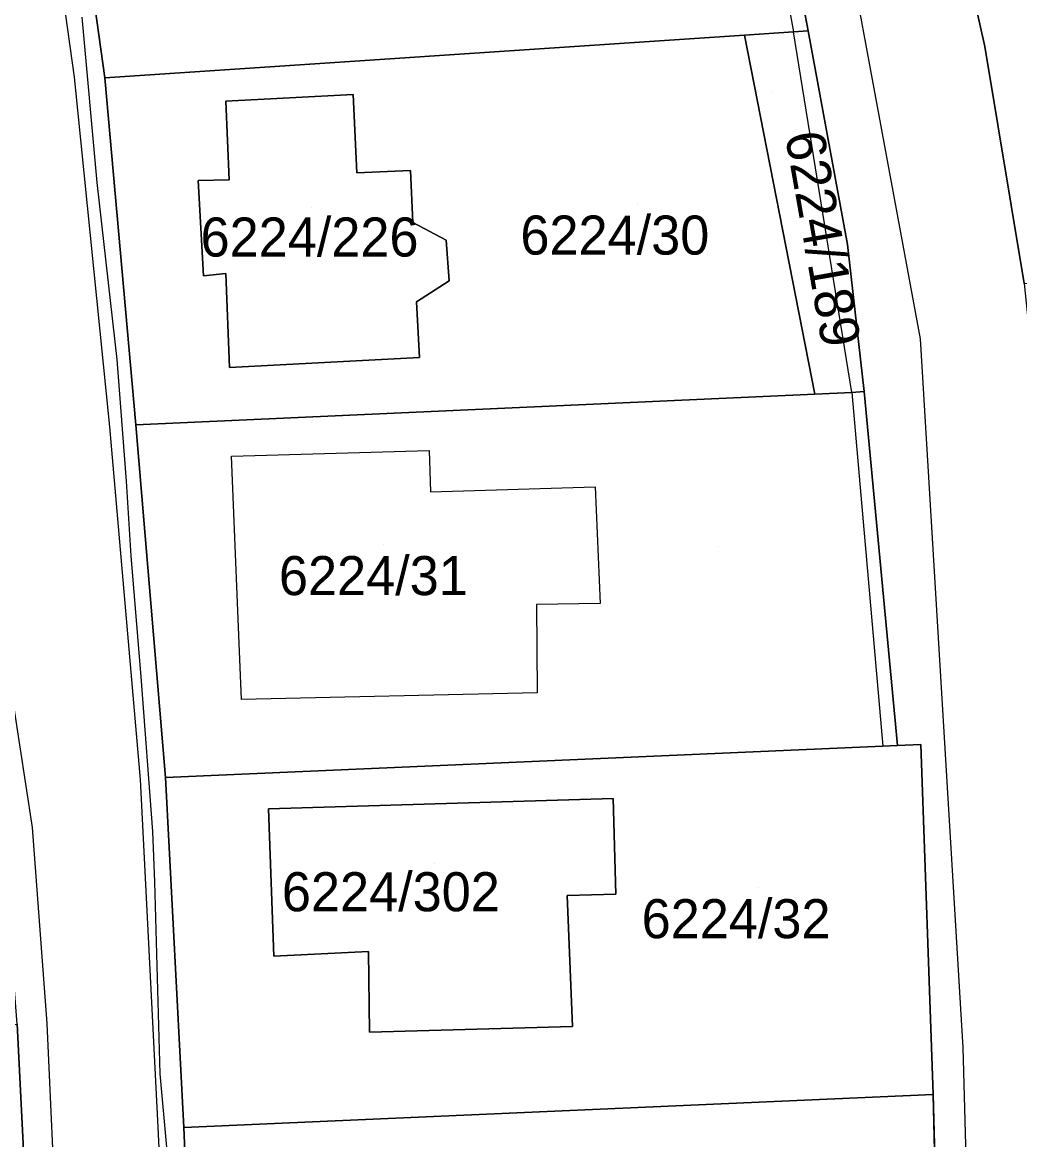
# Model space of a CAD drawing. Extents: x -266199 to -261993, y -1239047 to -1235108.
# Drawn here: x -263953.2 to -263902.2, y -1236099.8 to -1236042.6 of the extents above; entities that cross this region are included whole.
import ezdxf

# ---------------------------------------------------------------- set-up
doc = ezdxf.new("R2010")
doc.units = 0
for name, color, linetype in [('body_kn', 7, 'Continuous'), ('kladpar_druhypozemkov', 7, 'Continuous'), ('kladpar_hranice', 7, 'Continuous'), ('kladpar_parcelnecisla', 7, 'Continuous'), ('kladpar_plochy', 7, 'Continuous'), ('tarchy_linie', 7, 'Continuous'), ('zappar_hrandruhpozemk', 7, 'Continuous')]:
    doc.layers.add(name, color=color, linetype=linetype)

msp = doc.modelspace()

# ---------------------------------------------------------------- linework, layer by layer
at = {"layer": 'body_kn'}
for p, q in [((-263916.29, -1236043.3), (-263916.29, -1236043.3)), ((-263916.29, -1236043.3), (-263916.29, -1236043.3)), ((-263913.78, -1236043.13), (-263913.78, -1236043.13)), ((-263913.03, -1236043.08), (-263913.03, -1236043.08)), ((-263913.03, -1236043.08), (-263913.03, -1236043.08)), ((-263903.98, -1236043.88), (-263903.98, -1236043.88)), ((-263950.6, -1236045.45), (-263950.6, -1236045.45)), ((-263949.02, -1236045.48), (-263949.02, -1236045.48)), ((-263936.31, -1236046.34), (-263936.31, -1236046.34)), ((-263942.83, -1236046.68), (-263942.83, -1236046.68)), ((-263936.13, -1236050.35), (-263936.13, -1236050.35)), ((-263933.39, -1236050.22), (-263933.39, -1236050.22)), ((-263949.44, -1236050.84), (-263949.44, -1236050.84)), ((-263944.25, -1236050.74), (-263944.25, -1236050.74)), ((-263942.67, -1236050.71), (-263942.67, -1236050.71)), ((-263933.27, -1236052.89), (-263933.27, -1236052.89)), ((-263931.55, -1236053.79), (-263931.55, -1236053.79)), ((-263911.02, -1236054.02), (-263911.02, -1236054.02)), ((-263942.83, -1236055.5), (-263942.83, -1236055.5)), ((-263943.98, -1236055.62), (-263943.98, -1236055.62)), ((-263931.41, -1236055.87), (-263931.41, -1236055.87)), ((-263933.08, -1236056.95), (-263933.08, -1236056.95)), ((-263907.3, -1236058.84), (-263907.3, -1236058.84)), ((-263948.41, -1236059.9), (-263948.41, -1236059.9)), ((-263932.93, -1236059.79), (-263932.93, -1236059.79)), ((-263932.93, -1236059.79), (-263932.93, -1236059.79)), ((-263942.65, -1236060.31), (-263942.65, -1236060.31)), ((-263912.68, -1236061.67), (-263912.68, -1236061.67)), ((-263912.68, -1236061.67), (-263912.68, -1236061.67)), ((-263910.8, -1236061.59), (-263910.8, -1236061.59)), ((-263910.8, -1236061.59), (-263910.8, -1236061.59)), ((-263910.17, -1236061.54), (-263910.17, -1236061.54)), ((-263910.17, -1236061.54), (-263910.17, -1236061.54)), ((-263948.79, -1236063.35), (-263948.79, -1236063.35)), ((-263947.44, -1236063.25), (-263947.44, -1236063.25)), ((-263932.42, -1236064.56), (-263932.42, -1236064.56)), ((-263932.42, -1236064.56), (-263932.42, -1236064.56)), ((-263942.55, -1236064.85), (-263942.55, -1236064.85)), ((-263947.94, -1236066.13), (-263947.94, -1236066.13)), ((-263932.36, -1236066.67), (-263932.36, -1236066.67)), ((-263923.93, -1236066.41), (-263923.93, -1236066.41)), ((-263947.7, -1236069.95), (-263947.7, -1236069.95)), ((-263926.94, -1236072.44), (-263926.94, -1236072.44)), ((-263923.68, -1236072.38), (-263923.68, -1236072.38)), ((-263942.17, -1236074.01), (-263942.17, -1236074.01)), ((-263947.19, -1236076.14), (-263947.19, -1236076.14)), ((-263926.9, -1236076.96), (-263926.9, -1236076.96)), ((-263942.03, -1236077.3), (-263942.03, -1236077.3)), ((-263909.21, -1236079.69), (-263909.21, -1236079.69)), ((-263908.46, -1236079.66), (-263908.46, -1236079.66)), ((-263908.46, -1236079.66), (-263908.46, -1236079.66)), ((-263907.26, -1236079.6), (-263907.26, -1236079.6)), ((-263947.22, -1236081.4), (-263947.22, -1236081.4)), ((-263945.93, -1236081.29), (-263945.93, -1236081.29)), ((-263923.01, -1236082.36), (-263923.01, -1236082.36)), ((-263940.65, -1236082.9), (-263940.65, -1236082.9)), ((-263952.74, -1236083.86), (-263952.74, -1236083.86)), ((-263946.58, -1236084.06), (-263946.58, -1236084.06)), ((-263946.48, -1236086.64), (-263946.48, -1236086.64)), ((-263925.36, -1236087.34), (-263925.36, -1236087.34)), ((-263922.88, -1236087.27), (-263922.88, -1236087.27)), ((-263935.54, -1236090.2), (-263935.54, -1236090.2)), ((-263940.37, -1236090.43), (-263940.37, -1236090.43)), ((-263940.37, -1236090.43), (-263940.37, -1236090.43)), ((-263952, -1236093.88), (-263952, -1236093.88)), ((-263935.48, -1236094.33), (-263935.48, -1236094.33)), ((-263925.1, -1236094.03), (-263925.1, -1236094.03)), ((-263905.11, -1236095.12), (-263905.11, -1236095.12)), ((-263946.21, -1236096.46), (-263946.21, -1236096.46)), ((-263906.64, -1236097.52), (-263906.64, -1236097.52)), ((-263906.64, -1236097.52), (-263906.64, -1236097.52)), ((-263946.31, -1236099.19), (-263946.31, -1236099.19)), ((-263944.98, -1236099.21), (-263944.98, -1236099.21))]:
    msp.add_line(p, q, dxfattribs=at)
at = {"layer": 'kladpar_druhypozemkov'}
for p, q in [((-263914.88, -1236046.24), (-263914.88, -1236046.24)), ((-263921.79, -1236051.93), (-263921.79, -1236051.93)), ((-263938.44, -1236052.12), (-263938.44, -1236052.12)), ((-263934.74, -1236069.36), (-263934.74, -1236069.36)), ((-263917.6, -1236069.49), (-263917.6, -1236069.49)), ((-263932.16, -1236085.68), (-263932.16, -1236085.68)), ((-263915.59, -1236086.92), (-263915.59, -1236086.92))]:
    msp.add_line(p, q, dxfattribs=at)
at = {"layer": 'kladpar_hranice'}
for p, q in [((-263912.68, -1236061.67), (-263916.29, -1236043.3)), ((-263916.29, -1236043.3), (-263912.68, -1236061.67))]:
    msp.add_line(p, q, dxfattribs=at)
for points in [[(-263931.95, -1235931.45), (-263933.49, -1235931.8), (-263932.86, -1235934.73), (-263931.28, -1235934.37), (-263926.76, -1235952.23), (-263922.95, -1235967.01), (-263919.11, -1235980.52), (-263917.55, -1235986.2), (-263915.46, -1235994.07), (-263907.95, -1236026.19), (-263903.98, -1236043.88), (-263901.98, -1236056.01), (-263900.28, -1236072.34), (-263899.11, -1236091.36), (-263898.02, -1236125.27), (-263896.72, -1236166.69), (-263896.19, -1236183.38), (-263895.58, -1236202.24)], [(-263904.96, -1236148.67), (-263905.67, -1236133.58), (-263905.73, -1236131.33), (-263906.15, -1236115.51), (-263906.64, -1236097.52), (-263907.26, -1236079.6), (-263908.46, -1236079.66), (-263910.17, -1236061.54), (-263911.02, -1236054.02), (-263913.03, -1236043.08), (-263916.34, -1236025.48), (-263920.24, -1236009.49), (-263924.3, -1235992.9), (-263925.59, -1235988.88), (-263926.88, -1235984.79), (-263932, -1235968.58), (-263935.45, -1235956.55)], [(-263967.64, -1235962.02), (-263961.65, -1235978.64), (-263958, -1235993.19), (-263957.56, -1235994.94), (-263957.27, -1235996.1), (-263954.18, -1236011.08), (-263951.5, -1236027.74), (-263949.02, -1236045.48), (-263947.44, -1236063.25), (-263945.93, -1236081.29), (-263944.98, -1236099.21), (-263944.22, -1236117.2), (-263943.46, -1236135.24), (-263942.94, -1236150.22), (-263942.42, -1236165.25), (-263941.74, -1236180.26), (-263941.12, -1236196.31)], [(-263916.34, -1236025.48), (-263913.03, -1236043.08), (-263913.78, -1236043.13), (-263916.29, -1236043.3), (-263949.02, -1236045.48), (-263951.5, -1236027.74), (-263916.99, -1236025.52), (-263916.34, -1236025.48)], [(-263873.21, -1236037.96), (-263872.31, -1236056.62), (-263901.98, -1236056.01), (-263903.98, -1236043.88), (-263907.95, -1236026.19), (-263875.05, -1236025.74), (-263873.21, -1236037.96)], [(-263949.46, -1236197.58), (-263950.24, -1236172.84), (-263951.14, -1236149.91), (-263951.91, -1236127.77), (-263952.67, -1236110.92), (-263953.52, -1236093.92), (-263954.28, -1236083.99), (-263955.31, -1236076.7), (-263955.77, -1236073.5), (-263956.3, -1236069.59), (-263956.39, -1236069.23), (-263956.67, -1236068.06), (-263957.55, -1236066.3), (-263958.54, -1236061.71), (-263960.89, -1236058.94), (-263963.25, -1236055.69), (-263967.62, -1236055.28), (-263967.92, -1236051.04), (-263968.71, -1236039.76)], [(-263912.68, -1236061.67), (-263947.44, -1236063.25), (-263949.02, -1236045.48), (-263916.29, -1236043.3)], [(-263916.29, -1236043.3), (-263913.78, -1236043.13), (-263913.03, -1236043.08)], [(-263913.03, -1236043.08), (-263911.02, -1236054.02), (-263910.17, -1236061.54), (-263910.8, -1236061.59), (-263912.68, -1236061.67)], [(-263942.65, -1236060.31), (-263932.93, -1236059.79), (-263933.08, -1236056.95), (-263931.41, -1236055.87), (-263931.55, -1236053.79), (-263933.27, -1236052.89), (-263933.39, -1236050.22), (-263936.13, -1236050.35), (-263936.31, -1236046.34), (-263942.83, -1236046.68), (-263942.67, -1236050.71), (-263944.25, -1236050.74), (-263943.98, -1236055.62), (-263942.83, -1236055.5), (-263942.65, -1236060.31)], [(-263932.93, -1236059.79), (-263942.65, -1236060.31), (-263942.83, -1236055.5), (-263943.98, -1236055.62), (-263944.25, -1236050.74), (-263942.67, -1236050.71), (-263942.83, -1236046.68), (-263936.31, -1236046.34), (-263936.13, -1236050.35), (-263933.39, -1236050.22), (-263933.27, -1236052.89), (-263931.55, -1236053.79), (-263931.41, -1236055.87), (-263933.08, -1236056.95), (-263932.93, -1236059.79)], [(-263910.17, -1236061.54), (-263908.46, -1236079.66), (-263909.21, -1236079.69), (-263945.93, -1236081.29), (-263947.44, -1236063.25), (-263912.68, -1236061.67), (-263910.8, -1236061.59), (-263910.17, -1236061.54)], [(-263908.46, -1236079.66), (-263907.26, -1236079.6), (-263906.64, -1236097.52), (-263944.98, -1236099.21), (-263945.93, -1236081.29), (-263909.21, -1236079.69), (-263908.46, -1236079.66)], [(-263940.65, -1236082.9), (-263940.37, -1236090.43), (-263935.54, -1236090.2), (-263935.48, -1236094.33), (-263925.1, -1236094.03), (-263925.36, -1236087.34), (-263922.88, -1236087.27), (-263923.01, -1236082.36), (-263940.65, -1236082.9)], [(-263940.37, -1236090.43), (-263940.65, -1236082.9), (-263923.01, -1236082.36), (-263922.88, -1236087.27), (-263925.36, -1236087.34), (-263925.1, -1236094.03), (-263935.48, -1236094.33), (-263935.54, -1236090.2), (-263940.37, -1236090.43)], [(-263953.52, -1236093.92), (-263952.67, -1236110.92), (-263995.69, -1236113.37), (-263992.35, -1236096.02), (-263953.52, -1236093.92)], [(-263906.64, -1236097.52), (-263906.15, -1236115.51), (-263944.22, -1236117.2), (-263944.98, -1236099.21), (-263906.64, -1236097.52)]]:
    msp.add_lwpolyline(points, dxfattribs=at)
at = {"layer": 'kladpar_plochy'}
for p, q in [((-263913.03, -1236043.08), (-263916.34, -1236025.48)), ((-263903.98, -1236043.88), (-263907.95, -1236026.19)), ((-263907.95, -1236026.19), (-263903.98, -1236043.88)), ((-263949.02, -1236045.48), (-263916.29, -1236043.3)), ((-263916.29, -1236043.3), (-263912.68, -1236061.67)), ((-263911.02, -1236054.02), (-263913.03, -1236043.08)), ((-263901.98, -1236056.01), (-263903.98, -1236043.88)), ((-263903.98, -1236043.88), (-263901.98, -1236056.01)), ((-263947.44, -1236063.25), (-263949.02, -1236045.48)), ((-263936.31, -1236046.34), (-263942.83, -1236046.68)), ((-263936.13, -1236050.35), (-263936.31, -1236046.34)), ((-263942.83, -1236046.68), (-263942.67, -1236050.71)), ((-263933.39, -1236050.22), (-263936.13, -1236050.35)), ((-263933.27, -1236052.89), (-263933.39, -1236050.22)), ((-263942.67, -1236050.71), (-263944.25, -1236050.74)), ((-263944.25, -1236050.74), (-263943.98, -1236055.62)), ((-263931.55, -1236053.79), (-263933.27, -1236052.89)), ((-263931.41, -1236055.87), (-263931.55, -1236053.79)), ((-263910.17, -1236061.54), (-263911.02, -1236054.02)), ((-263943.98, -1236055.62), (-263942.83, -1236055.5)), ((-263942.83, -1236055.5), (-263942.65, -1236060.31)), ((-263933.08, -1236056.95), (-263931.41, -1236055.87)), ((-263932.93, -1236059.79), (-263933.08, -1236056.95)), ((-263942.65, -1236060.31), (-263932.93, -1236059.79)), ((-263912.68, -1236061.67), (-263947.44, -1236063.25)), ((-263908.46, -1236079.66), (-263910.17, -1236061.54)), ((-263945.93, -1236081.29), (-263909.21, -1236079.69)), ((-263909.21, -1236079.69), (-263908.46, -1236079.66)), ((-263908.46, -1236079.66), (-263907.26, -1236079.6)), ((-263907.26, -1236079.6), (-263908.46, -1236079.66)), ((-263907.26, -1236079.6), (-263906.64, -1236097.52)), ((-263906.64, -1236097.52), (-263907.26, -1236079.6)), ((-263944.98, -1236099.21), (-263945.93, -1236081.29)), ((-263923.01, -1236082.36), (-263940.65, -1236082.9)), ((-263922.88, -1236087.27), (-263923.01, -1236082.36)), ((-263940.65, -1236082.9), (-263940.37, -1236090.43)), ((-263925.36, -1236087.34), (-263922.88, -1236087.27)), ((-263925.1, -1236094.03), (-263925.36, -1236087.34)), ((-263940.37, -1236090.43), (-263935.54, -1236090.2)), ((-263935.54, -1236090.2), (-263935.48, -1236094.33)), ((-263935.48, -1236094.33), (-263925.1, -1236094.03)), ((-263906.64, -1236097.52), (-263944.98, -1236099.21)), ((-263906.15, -1236115.51), (-263906.64, -1236097.52))]:
    msp.add_line(p, q, dxfattribs=at)
for points in [[(-263967.64, -1235962.02), (-263961.65, -1235978.64), (-263958, -1235993.19), (-263957.56, -1235994.94), (-263957.27, -1235996.1), (-263954.18, -1236011.08), (-263951.5, -1236027.74), (-263949.02, -1236045.48), (-263947.44, -1236063.25), (-263945.93, -1236081.29), (-263944.98, -1236099.21), (-263944.22, -1236117.2), (-263943.46, -1236135.24), (-263942.94, -1236150.22), (-263942.42, -1236165.25), (-263941.74, -1236180.26), (-263941.12, -1236196.31)], [(-263949.46, -1236197.58), (-263950.24, -1236172.84), (-263951.14, -1236149.91), (-263951.91, -1236127.77), (-263952.67, -1236110.92), (-263953.52, -1236093.92), (-263954.28, -1236083.99), (-263955.31, -1236076.7), (-263955.77, -1236073.5), (-263956.3, -1236069.59), (-263956.39, -1236069.23), (-263956.67, -1236068.06), (-263957.55, -1236066.3), (-263958.54, -1236061.71), (-263960.89, -1236058.94), (-263963.25, -1236055.69), (-263967.62, -1236055.28), (-263967.92, -1236051.04), (-263968.71, -1236039.76)]]:
    msp.add_lwpolyline(points, dxfattribs=at)
for points in [[(-263916.34, -1236025.48), (-263913.03, -1236043.08), (-263913.78, -1236043.13), (-263916.29, -1236043.3), (-263949.02, -1236045.48), (-263951.5, -1236027.74), (-263916.99, -1236025.52)], [(-263913.03, -1236043.08), (-263911.02, -1236054.02), (-263910.17, -1236061.54), (-263910.8, -1236061.59), (-263912.68, -1236061.67), (-263916.29, -1236043.3), (-263913.78, -1236043.13)], [(-263932.93, -1236059.79), (-263942.65, -1236060.31), (-263942.83, -1236055.5), (-263943.98, -1236055.62), (-263944.25, -1236050.74), (-263942.67, -1236050.71), (-263942.83, -1236046.68), (-263936.31, -1236046.34), (-263936.13, -1236050.35), (-263933.39, -1236050.22), (-263933.27, -1236052.89), (-263931.55, -1236053.79), (-263931.41, -1236055.87), (-263933.08, -1236056.95)], [(-263910.17, -1236061.54), (-263908.46, -1236079.66), (-263909.21, -1236079.69), (-263945.93, -1236081.29), (-263947.44, -1236063.25), (-263912.68, -1236061.67), (-263910.8, -1236061.59)], [(-263940.37, -1236090.43), (-263940.65, -1236082.9), (-263923.01, -1236082.36), (-263922.88, -1236087.27), (-263925.36, -1236087.34), (-263925.1, -1236094.03), (-263935.48, -1236094.33), (-263935.54, -1236090.2)], [(-263953.52, -1236093.92), (-263952.67, -1236110.92), (-263995.69, -1236113.37), (-263992.35, -1236096.02)], [(-263906.64, -1236097.52), (-263906.15, -1236115.51), (-263944.22, -1236117.2), (-263944.98, -1236099.21)]]:
    msp.add_lwpolyline(points, close=True, dxfattribs=at)
at = {"layer": 'tarchy_linie'}
for points in [[(-263947.81, -1235901.98), (-263947.69, -1235903.35), (-263943.6, -1235905.78), (-263940.03, -1235926.05), (-263933.41, -1235953.88), (-263921.52, -1235995.74), (-263913.18, -1236027.02), (-263907.3, -1236058.84), (-263905.11, -1236095.12), (-263903.91, -1236139.53), (-263902.79, -1236171.66), (-263901.68, -1236205.85), (-263901.52, -1236222.46), (-263904.11, -1236228.02), (-263904.85, -1236229.61), (-263905.45, -1236229.43), (-263905.74, -1236230.7)], [(-263950.21, -1236042.38), (-263949.44, -1236050.84), (-263948.41, -1236059.9), (-263947.94, -1236066.13), (-263947.7, -1236069.95), (-263947.19, -1236076.14), (-263946.58, -1236084.06), (-263946.48, -1236086.64), (-263946.21, -1236096.46), (-263945.76, -1236101.52), (-263944.83, -1236119.44), (-263944.66, -1236126.25), (-263944.05, -1236144.27), (-263943.74, -1236155.25), (-263943.49, -1236158.82), (-263943.13, -1236169.18), (-263942.42, -1236184.1), (-263942.36, -1236189.25)]]:
    msp.add_lwpolyline(points, dxfattribs=at)
at = {"layer": 'zappar_hrandruhpozemk'}
for p, q in [((-263916.99, -1236025.52), (-263913.78, -1236043.13)), ((-263910.8, -1236061.59), (-263913.78, -1236043.13)), ((-263910.8, -1236061.59), (-263909.21, -1236079.69)), ((-263923.93, -1236066.41), (-263923.68, -1236072.38))]:
    msp.add_line(p, q, dxfattribs=at)
for points in [[(-263955.82, -1236011.36), (-263953.03, -1236027.99), (-263950.6, -1236045.45), (-263948.79, -1236063.35), (-263947.22, -1236081.4), (-263946.31, -1236099.19), (-263945.47, -1236117.22)], [(-263956.7, -1236060.49), (-263955.65, -1236066.49), (-263955.09, -1236069.33), (-263954.37, -1236073.28), (-263952.74, -1236083.86), (-263952, -1236093.88), (-263951.2, -1236111.56)], [(-263923.68, -1236072.38), (-263926.94, -1236072.44), (-263926.9, -1236076.96), (-263942.03, -1236077.3), (-263942.17, -1236074.01), (-263942.55, -1236064.85), (-263932.42, -1236064.56)], [(-263932.42, -1236064.56), (-263932.36, -1236066.67), (-263923.93, -1236066.41)]]:
    msp.add_lwpolyline(points, dxfattribs=at)

# ---------------------------------------------------------------- texts
at = {"layer": 'kladpar_parcelnecisla'}
msp.add_text('6224/189', height=2, rotation=280, dxfattribs=at).set_placement((-263914.223, -1236048.392))
for s, p in [('6224/226', (-263944.128, -1236054.63)), ('6224/30', (-263927.758, -1236054.53)), ('6224/31', (-263940.117, -1236071.96)), ('6224/302', (-263939.966, -1236088.14)), ('6224/32', (-263921.553, -1236089.52))]:
    msp.add_text(s, height=2, dxfattribs=at).set_placement(p)

doc.saveas('drawing.dxf')
